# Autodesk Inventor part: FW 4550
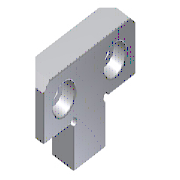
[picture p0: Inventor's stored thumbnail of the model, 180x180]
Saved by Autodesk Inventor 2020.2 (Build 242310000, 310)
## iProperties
Manager: www.cadconsulting.pl
Company: Fabian Stasiak CAD Consulting
Created: 2014-02
Part Number: FW 4550
Material: 1.7131
Description: Straight interlocks
Document SubType Name: Modeling
Designer: F.Stasiak
Standard Revision: 1
Manufacturer: DME
Language: pl-PL
Size Designation: 50
Categories: <MemberInstance><Categories><Category DisplayName="Forma wtryskowa" InternalName="349578f2-f4d4-4954-8c09-8e99297a61c0" Mnemonic="MOLD"><Category DisplayName="E
Density: 7.85 g/cm^3
Appearance: Domyślna
Catalog Web Link: www.expertbooks.pl
IsCustomPart: 1
Author: F.Stasiak
Subject: Zbiór ćwiczeń. Autodesk Inventor 2020. Kurs Professional
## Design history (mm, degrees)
sketch "Sketch1"
  geometry: L1 (-11, 0)-(-25, 0); L2 (-25, 0)-(-25, 17); L3 (-25, 17)-(25, 17); L4 (25, 17)-(25, 0); L5 (25, 0)-(11, 0); L6 (10, -1)-(10, -18); L7 (10, -18)-(-10, -18); L8 (-10, -18)-(-10, -1); L9 (0, 23.2)-(0, -20.2) reference; L10 (-28, 0)-(28, 0) reference; A1 r 1 centre (-10, 0) between (-10, -1) and (-11, 0); A2 r 1 centre (10, 0) between (11, 0) and (10, -1); 1 further point
  constraints: 16 end point, 6 point on line, 4 parallel, 4 point on circle, 3 collinear, 2 centre point, 1 horizontal, 1 perpendicular, 1 vertical, 2 other
  dimensions: "d0" = 50 distance between parallel lines of L2 L4 (= b); "d1" = 17 distance between parallel lines of L3 L1 (= s_); "d2" = 35 distance between parallel lines of L3 L7 (= l_); "d3" = 20 distance between parallel lines of L8 L6 (= b1); "d6" = 2 diameter of A1 (= R3); "d7" = 2 diameter of A2 (= R3)
extrude "Extrusion1" new body sketch "Sketch1" distance "d4" = 12.5 (= h_); taper "d5" = 0 deg
sketch "Sketch2"
  geometry: L1 (-17, 25)-(-17, -25) reference; L2 (0, 0)-(-21.442, 0); 2 further points
  constraints: 2 end point, 1 perpendicular, 1 symmetric about line
  dimensions: "d8" = 8.5 distance from line of L1 point (-8.5, 16) (= a1); "d10" = 32 distance of point (-8.5, 16) point (-8.5, -16) (= b2)
hole "Hole1" sketch "Sketch2" diameter "d11" = 6.6 (= D2); stored, may be unused: countersink angle "d15" = 90 deg, drill point angle "d17" = 0 deg; dims "d12" = 6, "d13" = 11 (= D1), "d14" = 6 (= M), "d16" = 12.5 (= h_)
hole "Hole2" sketch "Sketch2" diameter "d36" = 6.6 (= D2); stored, may be unused: countersink angle "d40" = 90 deg, drill point angle "d42" = 0 deg; dims "d37" = 6, "d38" = 11 (= D1), "d39" = 6 (= M), "d41" = 12.5 (= h_)
chamfer "Chamfer1" distance "d18" = 3 (= f1); stored, may be unused: second distance "d19" = 2, angle "d20" = 45 deg
chamfer "Chamfer2" distance "d21" = 6.5 (= f_); stored, may be unused: second distance "d22" = 2, angle "d23" = 45 deg
sketch "Sketch4"
  geometry: L1 (-18, 10)-(0, 10); L2 (0, 10)-(0, -10); L3 (0, -10)-(-18, -10); L4 (-18, -10)-(-18, 10); L5 (-18, 10)-(-1, 10) reference; L6 (-18, -10)-(-18, 10) reference; L7 (-1, -10)-(-18, -10) reference; L8 (0, 11)-(0, 18.5) reference; 1 further point
  constraints: 8 end point, 4 collinear, 2 parallel, 1 horizontal, 1 perpendicular
extrude "Extrusion2" cut sketch "Sketch4" distance "d24" = 1 (= h05); taper "d25" = 0 deg
fillet "Fillet1" dims "d26" = 0.5 (= 0.5 x h05)
sketch "Sketch5"
  geometry: L1 (14, 25)-(0.5, 25) reference; L2 (17, -19)-(17, 19) reference; L3 (0.5, -25)-(14, -25) reference; L4 (-18, 9.5)-(-18, -9.5) reference; L5 (-18, 25)-(17, 25); L6 (17, 25)-(17, -25); L7 (17, -25)-(-18, -25); L8 (-18, -25)-(-18, 25); 1 further point
  constraints: 8 end point, 4 collinear, 2 parallel, 1 horizontal, 1 perpendicular
extrude_surface "ExtrusionSrf1" sketch "Sketch5" dims "d27" = 25 (= 2 x h_), "d28" = 0
fillet "Fillet2" dims "d29" = 2 (= R3)
feature "Stitch Surface1" dims "d43" = 0.254 (derived)
body "Solid1"
body "Srf1"
body "Srf2"
body "Srf3"
body "Srf4"
patch "Boundary Patch1" dims "d30" = 0, "d31" = 0, "d32" = 0
patch "Boundary Patch2" dims "d33" = 0, "d34" = 0, "d35" = 0
other parameters: "b" = 50 [user parameter; used in 1 equation term], "a1" = 8.5 [user parameter; used in 1 equation term], "b1" = 20 [user parameter; used in 1 equation term], "b2" = 32 [user parameter; used in 1 equation term], "f_" = 6.5 [user parameter; used in 1 equation term], "f1" = 3 [user parameter; used in 1 equation term], "h_" = 12.5 [user parameter; used in 4 equation terms], "l_" = 35 [user parameter; used in 1 equation term], "s_" = 17 [user parameter; used in 1 equation term], "D1" = 11 [user parameter; used in 2 equation terms], "D2" = 6.6 [user parameter; used in 2 equation terms], "M" = 6 [user parameter; used in 2 equation terms], "h05" = 1 [user parameter; used in 2 equation terms], "R3" = 2 [user parameter; used in 3 equation terms]
